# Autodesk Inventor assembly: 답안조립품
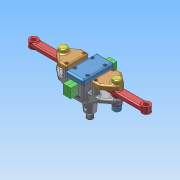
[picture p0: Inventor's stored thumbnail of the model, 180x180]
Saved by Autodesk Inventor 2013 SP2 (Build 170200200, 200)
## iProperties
Created: 2025-07
Part Number: 답안조립품
Document SubType Name: Assembly
Designer: a
Author: a
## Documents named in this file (11)
- C:\Users\a\Desktop\750703V1006\답안조립품.iam
- C:\Users\a\Desktop\750703V1006\본체.ipt
- C:\Users\a\Desktop\750703V1006\6각 구멍붙이 볼트 M3x10.ipt
- C:\Users\a\Desktop\750703V1006\6각 너트 M8.ipt
- C:\Users\a\Desktop\750703V1006\링크 커버.ipt
- C:\Users\a\Desktop\750703V1006\링크.ipt
- C:\Users\a\Desktop\750703V1006\스프링 와셔 M8.ipt
- C:\Users\a\Desktop\750703V1006\슬라이더 커버.ipt
- C:\Users\a\Desktop\750703V1006\슬라이더.ipt
- C:\Users\a\Desktop\750703V1006\평 와셔 M8.ipt
- C:\Users\a\Desktop\750703V1006\핀.ipt
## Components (12 placed, 3 different names)
1. 6각 구멍붙이 볼트 M3x10:1
2. 6각 너트 M8:1
3. 핀:1 — 각도:3
4. 핀:2 — 각도:4
5. 6각 너트 M8:2
6. 6각 구멍붙이 볼트 M3x10:2
7. 6각 구멍붙이 볼트 M3x10:3
8. 6각 구멍붙이 볼트 M3x10:4
9. 6각 구멍붙이 볼트 M3x10:5
10. 6각 구멍붙이 볼트 M3x10:6
11. 6각 구멍붙이 볼트 M3x10:7
12. 6각 구멍붙이 볼트 M3x10:8
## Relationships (2: Angle 2)
- 각도:3 [Angle]: 핀:1
- 각도:4 [Angle]: 핀:2
